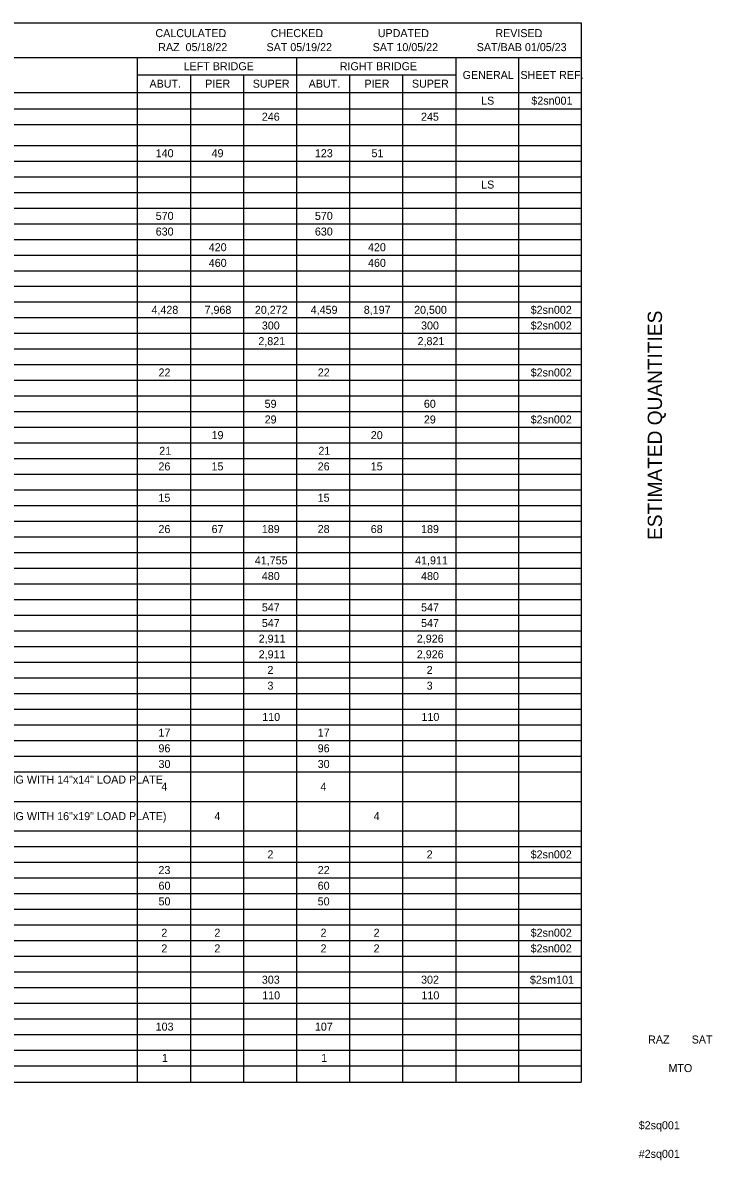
# Model space of a CAD drawing. Extents: x -62.6 to 33.3, y -2.9 to 24.9.
# Drawn here: x 21.24 to 33.3, y 0.56 to 20.46 of the extents above; entities that cross this region are included whole.
import ezdxf

# ---------------------------------------------------------------- set-up
doc = ezdxf.new("R2010")
doc.units = 0
for name, color, linetype in [('Default', 7, 'Continuous'), ('SH_Data', 7, 'Continuous'), ('SH_Major_Grid_Line', 7, 'Continuous')]:
    doc.layers.add(name, color=color, linetype=linetype)

msp = doc.modelspace()

# ---------------------------------------------------------------- linework, layer by layer
at = {"layer": 'Default'}
for p, q in [((2.248, 20.46), (31.009, 20.46)), ((31.009, 20.46), (31.009, 1.926)), ((2.248, 19.852), (31.009, 19.852)), ((23.248, 19.852), (23.248, 1.926)), ((26.033, 19.852), (26.033, 1.926)), ((28.818, 19.852), (28.818, 1.926)), ((29.913, 19.852), (29.913, 1.926)), ((23.248, 19.547), (28.818, 19.547)), ((24.176, 19.547), (24.176, 1.926)), ((25.105, 19.547), (25.105, 1.926)), ((26.961, 19.547), (26.961, 1.926)), ((27.889, 19.547), (27.889, 1.926)), ((2.248, 19.243), (31.009, 19.243)), ((2.248, 18.954), (31.009, 18.954)), ((2.248, 18.68), (31.009, 18.68)), ((2.248, 18.315), (31.009, 18.315)), ((2.248, 18.041), (31.009, 18.041)), ((2.248, 17.767), (31.009, 17.767)), ((2.248, 17.493), (31.009, 17.493)), ((2.248, 17.219), (31.009, 17.219)), ((2.248, 16.945), (31.009, 16.945)), ((2.248, 16.671), (31.009, 16.671)), ((2.248, 16.397), (31.009, 16.397)), ((2.248, 16.123), (31.009, 16.123)), ((2.248, 15.85), (31.009, 15.85)), ((2.248, 15.576), (31.009, 15.576)), ((2.248, 15.302), (31.009, 15.302)), ((2.248, 15.028), (31.009, 15.028)), ((2.248, 14.754), (31.009, 14.754)), ((2.248, 14.48), (31.009, 14.48)), ((2.248, 14.206), (31.009, 14.206)), ((2.248, 13.932), (31.009, 13.932)), ((2.248, 13.658), (31.009, 13.658)), ((2.248, 13.384), (31.009, 13.384)), ((2.248, 13.11), (31.009, 13.11)), ((2.248, 12.837), (31.009, 12.837)), ((2.248, 12.563), (31.009, 12.563)), ((2.248, 12.289), (31.009, 12.289)), ((2.248, 12.015), (31.009, 12.015)), ((2.248, 11.741), (31.009, 11.741)), ((2.248, 11.467), (31.009, 11.467)), ((2.248, 11.193), (31.009, 11.193)), ((2.248, 10.919), (31.009, 10.919)), ((2.248, 10.645), (31.009, 10.645)), ((2.248, 10.371), (31.009, 10.371)), ((2.248, 10.097), (31.009, 10.097)), ((2.248, 9.823), (31.009, 9.823)), ((2.248, 9.55), (31.009, 9.55)), ((2.248, 9.276), (31.009, 9.276)), ((2.248, 9.002), (31.009, 9.002)), ((2.248, 8.728), (31.009, 8.728)), ((2.248, 8.454), (31.009, 8.454)), ((2.248, 8.18), (31.009, 8.18)), ((2.248, 7.906), (31.009, 7.906)), ((2.248, 7.632), (31.009, 7.632)), ((2.248, 7.358), (31.009, 7.358)), ((2.248, 6.841), (31.009, 6.841)), ((2.248, 6.323), (31.009, 6.323)), ((2.248, 6.05), (31.009, 6.05)), ((2.248, 5.776), (31.009, 5.776)), ((2.248, 5.502), (31.009, 5.502)), ((2.248, 5.228), (31.009, 5.228)), ((2.248, 4.954), (31.009, 4.954)), ((2.248, 4.68), (31.009, 4.68)), ((2.248, 4.406), (31.009, 4.406)), ((2.248, 4.132), (31.009, 4.132)), ((2.248, 3.858), (31.009, 3.858)), ((2.248, 3.584), (31.009, 3.584)), ((2.248, 3.31), (31.009, 3.31)), ((2.248, 3.037), (31.009, 3.037)), ((2.248, 2.763), (31.009, 2.763)), ((2.248, 2.489), (31.009, 2.489)), ((2.248, 2.215), (31.009, 2.215)), ((2.248, 1.926), (31.009, 1.926))]:
    msp.add_line(p, q, dxfattribs=at)

# ---------------------------------------------------------------- texts
at = {"layer": 'SH_Data'}
for s, p in [('RAZ', (32.182, 2.605)), ('SAT', (32.944, 2.605)), ('MTO', (32.538, 2.105)), ('$2sq001', (32.018, 1.105)), ('#2sq001', (32.018, 0.605))]:
    msp.add_text(s, height=0.14, dxfattribs=at).set_placement(p)
at = {"layer": 'SH_Major_Grid_Line'}
for s, p in [('CALCULATED', (23.565, 20.209)), (':', (24.755, 20.209)), ('CHECKED', (25.581, 20.209)), (': ', (26.451, 20.209)), ('UPDATED', (27.454, 20.209)), (': ', (28.292, 20.209)), ('REVISED', (29.51, 20.209)), (': ', (30.283, 20.209)), ('RAZ  05/18/22', (23.614, 19.964)), ('SAT 05/19/22', (25.508, 19.964)), ('SAT 10/05/22', (27.364, 19.964)), ('SAT/BAB 01/05/23', (29.185, 19.964)), ('LEFT BRIDGE', (24.058, 19.63)), ('RIGHT BRIDGE', (26.789, 19.63)), ('GENERAL', (28.938, 19.477)), ('SHEET REF.', (29.949, 19.477)), ('ABUT.', (23.461, 19.325)), ('PIER', (24.436, 19.325)), ('SUPER', (25.267, 19.325)), ('ABUT.', (26.245, 19.325)), ('PIER', (27.221, 19.325)), ('SUPER', (28.051, 19.325)), ('LS', (29.262, 19.028)), ('$2sn001', (30.14, 19.028)), ('246', (25.426, 18.747)), ('245', (28.21, 18.747)), ('140', (23.57, 18.108)), ('49', (24.547, 18.108)), ('123', (26.354, 18.108)), ('51', (27.344, 18.108)), ('LS', (29.262, 17.56)), ('570', (23.57, 17.012)), ('570', (26.354, 17.012)), ('630', (23.57, 16.738)), ('630', (26.354, 16.738)), ('420', (24.498, 16.464)), ('420', (27.283, 16.464)), ('460', (24.498, 16.19)), ('460', (27.283, 16.19)), ('4,428', (23.496, 15.369)), ('7,968', (24.424, 15.369)), ('20,272', (25.304, 15.369)), ('4,459', (26.281, 15.369)), ('8,197', (27.209, 15.369)), ('20,500', (28.089, 15.369)), ('$2sn002', (30.128, 15.369)), ('300', (25.426, 15.095)), ('300', (28.211, 15.095)), ('$2sn002', (30.128, 15.095)), ('2,821', (25.365, 14.821)), ('2,821', (28.15, 14.821)), ('22', (23.619, 14.273)), ('22', (26.404, 14.273)), ('$2sn002', (30.128, 14.273)), ('59', (25.475, 13.725)), ('60', (28.26, 13.725)), ('29', (25.475, 13.451)), ('29', (28.26, 13.451)), ('$2sn002', (30.128, 13.451)), ('19', (24.547, 13.177)), ('20', (27.332, 13.177)), ('21', (23.631, 12.903)), ('21', (26.415, 12.903)), ('26', (23.618, 12.63)), ('15', (24.546, 12.63)), ('26', (26.403, 12.63)), ('15', (27.331, 12.63)), ('15', (23.618, 12.082)), ('15', (26.403, 12.082)), ('26', (23.618, 11.534)), ('67', (24.547, 11.534)), ('189', (25.426, 11.534)), ('28', (26.403, 11.534)), ('68', (27.331, 11.534)), ('189', (28.211, 11.534)), ('41,755', (25.303, 10.986)), ('41,911', (28.107, 10.986)), ('480', (25.426, 10.712)), ('480', (28.211, 10.712)), ('547', (25.426, 10.164)), ('547', (28.211, 10.164)), ('547', (25.426, 9.89)), ('547', (28.211, 9.89)), ('2,911', (25.371, 9.617)), ('2,926', (28.137, 9.617)), ('2,911', (25.371, 9.343)), ('2,926', (28.137, 9.343)), ('2', (25.524, 9.069)), ('2', (28.309, 9.069)), ('3', (25.524, 8.795)), ('3', (28.309, 8.795)), ('110', (25.433, 8.247)), ('110', (28.218, 8.247)), ('17', (23.618, 7.973)), ('17', (26.403, 7.973)), ('96', (23.618, 7.699)), ('96', (26.403, 7.699)), ('30', (23.619, 7.425)), ('30', (26.403, 7.425)), ('ELASTOMERIC BEARING WITH INTERNAL LAMINATES AND LOAD PLATE (NEOPRENE) (13"x13"x4.08" BEARING WITH 14"x14" LOAD PLATE ', (11.348, 7.152)), ('4', (23.668, 7.03)), ('4', (26.452, 7.03)), ('ELASTOMERIC BEARING WITH INTERNAL LAMINATES AND LOAD PLATE (NEOPRENE) (15"x18"x4.08" BEARING WITH 16"x19" LOAD PLATE)', (11.348, 6.512)), ('4', (24.596, 6.512)), ('4', (27.381, 6.512)), ('2', (25.524, 5.843)), ('2', (28.309, 5.843)), ('$2sn002', (30.128, 5.843)), ('23', (23.618, 5.569)), ('22', (26.404, 5.569)), ('60', (23.619, 5.295)), ('60', (26.403, 5.295)), ('50', (23.619, 5.021)), ('50', (26.403, 5.021)), ('2', (23.668, 4.473)), ('2', (24.596, 4.473)), ('2', (26.453, 4.473)), ('2', (27.381, 4.473)), ('$2sn002', (30.128, 4.473)), ('2', (23.668, 4.199)), ('2', (24.596, 4.199)), ('2', (26.453, 4.199)), ('2', (27.381, 4.199)), ('$2sn002', (30.128, 4.199)), ('303', (25.426, 3.651)), ('302', (28.211, 3.651)), ('$2sm101', (30.115, 3.651)), ('110', (25.433, 3.377)), ('110', (28.218, 3.377)), ('103', (23.569, 2.83)), ('107', (26.354, 2.83)), ('1', (23.679, 2.282)), ('1', (26.464, 2.282))]:
    msp.add_text(s, height=0.14, dxfattribs=at).set_placement(p)
msp.add_text('ESTIMATED QUANTITIES', height=0.25, rotation=90, dxfattribs=at).set_placement((32.425, 11.413))

doc.saveas('drawing.dxf')
